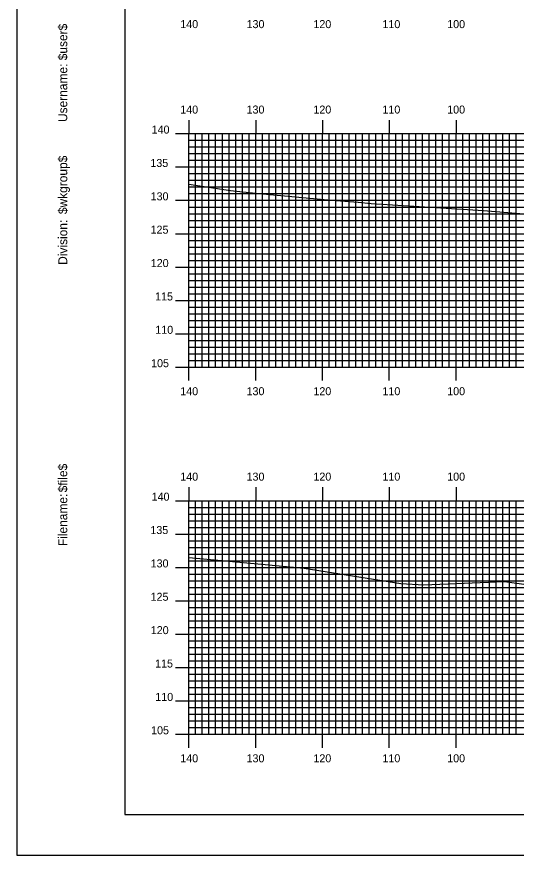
# Model space of a CAD drawing. Extents: x 1767300 to 1767643, y 442591 to 442811.
# Drawn here: x 1767300.1 to 1767375, y 442590.5 to 442716.2 of the extents above; entities that cross this region are included whole.
import ezdxf

# ---------------------------------------------------------------- set-up
doc = ezdxf.new("R2010")
doc.units = 0
for name, color, linetype in [('BORDER', 7, 'Continuous'), ('H_V ANNOTATION', 7, 'Continuous'), ('MAJOR', 7, 'Continuous'), ('MINOR', 7, 'Continuous'), ('PLOT BOUNDARY', 7, 'Continuous'), ('S_Roadway_Centerline', 7, 'Continuous')]:
    doc.layers.add(name, color=color, linetype=linetype)

msp = doc.modelspace()

# ---------------------------------------------------------------- linework, layer by layer
at = {"layer": 'BORDER'}
msp.add_lwpolyline([(1767316.34, 442596.67), (1767636.34, 442596.67), (1767636.34, 442806.67), (1767316.34, 442806.67)], close=True, dxfattribs=at)
at = {"layer": 'MAJOR'}
for p, q in [((1767325.94, 442700.67), (1767325.94, 442698.67)), ((1767335.94, 442700.67), (1767335.94, 442698.67)), ((1767345.94, 442700.67), (1767345.94, 442698.67)), ((1767355.94, 442700.67), (1767355.94, 442698.67)), ((1767365.94, 442700.67), (1767365.94, 442698.67)), ((1767323.93, 442698.67), (1767325.94, 442698.67)), ((1767325.94, 442698.67), (1767605.94, 442698.67)), ((1767325.94, 442663.67), (1767325.94, 442698.67)), ((1767325.94, 442663.67), (1767325.94, 442698.67)), ((1767325.94, 442698.67), (1767605.94, 442698.67)), ((1767335.94, 442663.67), (1767335.94, 442698.67)), ((1767345.94, 442663.67), (1767345.94, 442698.67)), ((1767355.94, 442663.67), (1767355.94, 442698.67)), ((1767365.94, 442663.67), (1767365.94, 442698.67)), ((1767323.93, 442693.67), (1767325.94, 442693.67)), ((1767325.94, 442693.67), (1767605.94, 442693.67)), ((1767323.93, 442688.67), (1767325.94, 442688.67)), ((1767325.94, 442688.67), (1767605.94, 442688.67)), ((1767323.93, 442683.67), (1767325.94, 442683.67)), ((1767325.94, 442683.67), (1767605.94, 442683.67)), ((1767323.93, 442678.67), (1767325.94, 442678.67)), ((1767325.94, 442678.67), (1767605.94, 442678.67)), ((1767323.93, 442673.67), (1767325.94, 442673.67)), ((1767325.94, 442673.67), (1767605.94, 442673.67)), ((1767323.93, 442668.67), (1767325.94, 442668.67)), ((1767325.94, 442668.67), (1767605.94, 442668.67)), ((1767323.93, 442663.67), (1767325.94, 442663.67)), ((1767325.94, 442663.67), (1767605.94, 442663.67)), ((1767325.94, 442663.67), (1767605.94, 442663.67)), ((1767325.94, 442661.66), (1767325.94, 442663.67)), ((1767335.94, 442661.66), (1767335.94, 442663.67)), ((1767345.94, 442661.66), (1767345.94, 442663.67)), ((1767355.94, 442661.66), (1767355.94, 442663.67)), ((1767365.94, 442661.66), (1767365.94, 442663.67)), ((1767325.94, 442645.67), (1767325.94, 442643.67)), ((1767335.94, 442645.67), (1767335.94, 442643.67)), ((1767345.94, 442645.67), (1767345.94, 442643.67)), ((1767355.94, 442645.67), (1767355.94, 442643.67)), ((1767365.94, 442645.67), (1767365.94, 442643.67)), ((1767323.93, 442643.67), (1767325.94, 442643.67)), ((1767325.94, 442643.67), (1767605.94, 442643.67)), ((1767325.94, 442608.67), (1767325.94, 442643.67)), ((1767325.94, 442608.67), (1767325.94, 442643.67)), ((1767325.94, 442643.67), (1767605.94, 442643.67)), ((1767335.94, 442608.67), (1767335.94, 442643.67)), ((1767345.94, 442608.67), (1767345.94, 442643.67)), ((1767355.94, 442608.67), (1767355.94, 442643.67)), ((1767365.94, 442608.67), (1767365.94, 442643.67)), ((1767323.93, 442638.67), (1767325.94, 442638.67)), ((1767325.94, 442638.67), (1767605.94, 442638.67)), ((1767323.93, 442633.67), (1767325.94, 442633.67)), ((1767325.94, 442633.67), (1767605.94, 442633.67)), ((1767323.93, 442628.67), (1767325.94, 442628.67)), ((1767325.94, 442628.67), (1767605.94, 442628.67)), ((1767323.93, 442623.67), (1767325.94, 442623.67)), ((1767325.94, 442623.67), (1767605.94, 442623.67)), ((1767323.93, 442618.67), (1767325.94, 442618.67)), ((1767325.94, 442618.67), (1767605.94, 442618.67)), ((1767323.93, 442613.67), (1767325.94, 442613.67)), ((1767325.94, 442613.67), (1767605.94, 442613.67)), ((1767323.93, 442608.67), (1767325.94, 442608.67)), ((1767325.94, 442608.67), (1767605.94, 442608.67)), ((1767325.94, 442608.67), (1767605.94, 442608.67)), ((1767325.94, 442606.66), (1767325.94, 442608.67)), ((1767335.94, 442606.66), (1767335.94, 442608.67)), ((1767345.94, 442606.66), (1767345.94, 442608.67)), ((1767355.94, 442606.66), (1767355.94, 442608.67)), ((1767365.94, 442606.66), (1767365.94, 442608.67))]:
    msp.add_line(p, q, dxfattribs=at)
at = {"layer": 'MINOR'}
for p, q in [((1767326.94, 442663.67), (1767326.94, 442698.67)), ((1767327.94, 442663.67), (1767327.94, 442698.67)), ((1767328.94, 442663.67), (1767328.94, 442698.67)), ((1767329.94, 442663.67), (1767329.94, 442698.67)), ((1767330.94, 442663.67), (1767330.94, 442698.67)), ((1767331.94, 442663.67), (1767331.94, 442698.67)), ((1767332.94, 442663.67), (1767332.94, 442698.67)), ((1767333.94, 442663.67), (1767333.94, 442698.67)), ((1767334.94, 442663.67), (1767334.94, 442698.67)), ((1767336.94, 442663.67), (1767336.94, 442698.67)), ((1767337.94, 442663.67), (1767337.94, 442698.67)), ((1767338.94, 442663.67), (1767338.94, 442698.67)), ((1767339.94, 442663.67), (1767339.94, 442698.67)), ((1767340.94, 442663.67), (1767340.94, 442698.67)), ((1767341.94, 442663.67), (1767341.94, 442698.67)), ((1767342.94, 442663.67), (1767342.94, 442698.67)), ((1767343.94, 442663.67), (1767343.94, 442698.67)), ((1767344.94, 442663.67), (1767344.94, 442698.67)), ((1767346.94, 442663.67), (1767346.94, 442698.67)), ((1767347.94, 442663.67), (1767347.94, 442698.67)), ((1767348.94, 442663.67), (1767348.94, 442698.67)), ((1767349.94, 442663.67), (1767349.94, 442698.67)), ((1767350.94, 442663.67), (1767350.94, 442698.67)), ((1767351.94, 442663.67), (1767351.94, 442698.67)), ((1767352.94, 442663.67), (1767352.94, 442698.67)), ((1767353.94, 442663.67), (1767353.94, 442698.67)), ((1767354.94, 442663.67), (1767354.94, 442698.67)), ((1767356.94, 442663.67), (1767356.94, 442698.67)), ((1767357.94, 442663.67), (1767357.94, 442698.67)), ((1767358.94, 442663.67), (1767358.94, 442698.67)), ((1767359.94, 442663.67), (1767359.94, 442698.67)), ((1767360.94, 442663.67), (1767360.94, 442698.67)), ((1767361.94, 442663.67), (1767361.94, 442698.67)), ((1767362.94, 442663.67), (1767362.94, 442698.67)), ((1767363.94, 442663.67), (1767363.94, 442698.67)), ((1767364.94, 442663.67), (1767364.94, 442698.67)), ((1767366.94, 442663.67), (1767366.94, 442698.67)), ((1767367.94, 442663.67), (1767367.94, 442698.67)), ((1767368.94, 442663.67), (1767368.94, 442698.67)), ((1767369.94, 442663.67), (1767369.94, 442698.67)), ((1767370.94, 442663.67), (1767370.94, 442698.67)), ((1767371.94, 442663.67), (1767371.94, 442698.67)), ((1767372.94, 442663.67), (1767372.94, 442698.67)), ((1767373.94, 442663.67), (1767373.94, 442698.67)), ((1767374.94, 442663.67), (1767374.94, 442698.67)), ((1767325.94, 442697.67), (1767605.94, 442697.67)), ((1767325.94, 442697.67), (1767327.94, 442697.67)), ((1767325.94, 442696.67), (1767605.94, 442696.67)), ((1767325.94, 442696.67), (1767327.94, 442696.67)), ((1767325.94, 442695.67), (1767605.94, 442695.67)), ((1767325.94, 442695.67), (1767327.94, 442695.67)), ((1767325.94, 442694.67), (1767605.94, 442694.67)), ((1767325.94, 442694.67), (1767327.94, 442694.67)), ((1767325.94, 442692.67), (1767605.94, 442692.67)), ((1767325.94, 442692.67), (1767327.94, 442692.67)), ((1767325.94, 442691.67), (1767605.94, 442691.67)), ((1767325.94, 442691.67), (1767327.94, 442691.67)), ((1767325.94, 442690.67), (1767605.94, 442690.67)), ((1767325.94, 442690.67), (1767327.94, 442690.67)), ((1767325.94, 442689.67), (1767605.94, 442689.67)), ((1767325.94, 442689.67), (1767327.94, 442689.67)), ((1767325.94, 442687.67), (1767605.94, 442687.67)), ((1767325.94, 442687.67), (1767327.94, 442687.67)), ((1767325.94, 442686.67), (1767605.94, 442686.67)), ((1767325.94, 442686.67), (1767327.94, 442686.67)), ((1767325.94, 442685.67), (1767605.94, 442685.67)), ((1767325.94, 442685.67), (1767327.94, 442685.67)), ((1767325.94, 442684.67), (1767605.94, 442684.67)), ((1767325.94, 442684.67), (1767327.94, 442684.67)), ((1767325.94, 442682.67), (1767605.94, 442682.67)), ((1767325.94, 442682.67), (1767327.94, 442682.67)), ((1767325.94, 442681.67), (1767605.94, 442681.67)), ((1767325.94, 442681.67), (1767327.94, 442681.67)), ((1767325.94, 442680.67), (1767605.94, 442680.67)), ((1767325.94, 442680.67), (1767327.94, 442680.67)), ((1767325.94, 442679.67), (1767605.94, 442679.67)), ((1767325.94, 442679.67), (1767327.94, 442679.67)), ((1767325.94, 442677.67), (1767605.94, 442677.67)), ((1767325.94, 442677.67), (1767327.94, 442677.67)), ((1767325.94, 442676.67), (1767605.94, 442676.67)), ((1767325.94, 442676.67), (1767327.94, 442676.67)), ((1767325.94, 442675.67), (1767605.94, 442675.67)), ((1767325.94, 442675.67), (1767327.94, 442675.67)), ((1767325.94, 442674.67), (1767605.94, 442674.67)), ((1767325.94, 442674.67), (1767327.94, 442674.67)), ((1767325.94, 442672.67), (1767605.94, 442672.67)), ((1767325.94, 442672.67), (1767327.94, 442672.67)), ((1767325.94, 442671.67), (1767605.94, 442671.67)), ((1767325.94, 442671.67), (1767327.94, 442671.67)), ((1767325.94, 442670.67), (1767605.94, 442670.67)), ((1767325.94, 442670.67), (1767327.94, 442670.67)), ((1767325.94, 442669.67), (1767605.94, 442669.67)), ((1767325.94, 442669.67), (1767327.94, 442669.67)), ((1767325.94, 442667.67), (1767605.94, 442667.67)), ((1767325.94, 442667.67), (1767327.94, 442667.67)), ((1767325.94, 442666.67), (1767605.94, 442666.67)), ((1767325.94, 442666.67), (1767327.94, 442666.67)), ((1767325.94, 442665.67), (1767605.94, 442665.67)), ((1767325.94, 442665.67), (1767327.94, 442665.67)), ((1767325.94, 442664.67), (1767605.94, 442664.67)), ((1767325.94, 442664.67), (1767327.94, 442664.67)), ((1767326.94, 442608.67), (1767326.94, 442643.67)), ((1767327.94, 442608.67), (1767327.94, 442643.67)), ((1767328.94, 442608.67), (1767328.94, 442643.67)), ((1767329.94, 442608.67), (1767329.94, 442643.67)), ((1767330.94, 442608.67), (1767330.94, 442643.67)), ((1767331.94, 442608.67), (1767331.94, 442643.67)), ((1767332.94, 442608.67), (1767332.94, 442643.67)), ((1767333.94, 442608.67), (1767333.94, 442643.67)), ((1767334.94, 442608.67), (1767334.94, 442643.67)), ((1767336.94, 442608.67), (1767336.94, 442643.67)), ((1767337.94, 442608.67), (1767337.94, 442643.67)), ((1767338.94, 442608.67), (1767338.94, 442643.67)), ((1767339.94, 442608.67), (1767339.94, 442643.67)), ((1767340.94, 442608.67), (1767340.94, 442643.67)), ((1767341.94, 442608.67), (1767341.94, 442643.67)), ((1767342.94, 442608.67), (1767342.94, 442643.67)), ((1767343.94, 442608.67), (1767343.94, 442643.67)), ((1767344.94, 442608.67), (1767344.94, 442643.67)), ((1767346.94, 442608.67), (1767346.94, 442643.67)), ((1767347.94, 442608.67), (1767347.94, 442643.67)), ((1767348.94, 442608.67), (1767348.94, 442643.67)), ((1767349.94, 442608.67), (1767349.94, 442643.67)), ((1767350.94, 442608.67), (1767350.94, 442643.67)), ((1767351.94, 442608.67), (1767351.94, 442643.67)), ((1767352.94, 442608.67), (1767352.94, 442643.67)), ((1767353.94, 442608.67), (1767353.94, 442643.67)), ((1767354.94, 442608.67), (1767354.94, 442643.67)), ((1767356.94, 442608.67), (1767356.94, 442643.67)), ((1767357.94, 442608.67), (1767357.94, 442643.67)), ((1767358.94, 442608.67), (1767358.94, 442643.67)), ((1767359.94, 442608.67), (1767359.94, 442643.67)), ((1767360.94, 442608.67), (1767360.94, 442643.67)), ((1767361.94, 442608.67), (1767361.94, 442643.67)), ((1767362.94, 442608.67), (1767362.94, 442643.67)), ((1767363.94, 442608.67), (1767363.94, 442643.67)), ((1767364.94, 442608.67), (1767364.94, 442643.67)), ((1767366.94, 442608.67), (1767366.94, 442643.67)), ((1767367.94, 442608.67), (1767367.94, 442643.67)), ((1767368.94, 442608.67), (1767368.94, 442643.67)), ((1767369.94, 442608.67), (1767369.94, 442643.67)), ((1767370.94, 442608.67), (1767370.94, 442643.67)), ((1767371.94, 442608.67), (1767371.94, 442643.67)), ((1767372.94, 442608.67), (1767372.94, 442643.67)), ((1767373.94, 442608.67), (1767373.94, 442643.67)), ((1767374.94, 442608.67), (1767374.94, 442643.67)), ((1767325.94, 442642.67), (1767605.94, 442642.67)), ((1767325.94, 442642.67), (1767327.94, 442642.67)), ((1767325.94, 442641.67), (1767605.94, 442641.67)), ((1767325.94, 442641.67), (1767327.94, 442641.67)), ((1767325.94, 442640.67), (1767605.94, 442640.67)), ((1767325.94, 442640.67), (1767327.94, 442640.67)), ((1767325.94, 442639.67), (1767605.94, 442639.67)), ((1767325.94, 442639.67), (1767327.94, 442639.67)), ((1767325.94, 442637.67), (1767605.94, 442637.67)), ((1767325.94, 442637.67), (1767327.94, 442637.67)), ((1767325.94, 442636.67), (1767605.94, 442636.67)), ((1767325.94, 442636.67), (1767327.94, 442636.67)), ((1767325.94, 442635.67), (1767605.94, 442635.67)), ((1767325.94, 442635.67), (1767327.94, 442635.67)), ((1767325.94, 442634.67), (1767605.94, 442634.67)), ((1767325.94, 442634.67), (1767327.94, 442634.67)), ((1767325.94, 442632.67), (1767605.94, 442632.67)), ((1767325.94, 442632.67), (1767327.94, 442632.67)), ((1767325.94, 442631.67), (1767605.94, 442631.67)), ((1767325.94, 442631.67), (1767327.94, 442631.67)), ((1767325.94, 442630.67), (1767605.94, 442630.67)), ((1767325.94, 442630.67), (1767327.94, 442630.67)), ((1767325.94, 442629.67), (1767605.94, 442629.67)), ((1767325.94, 442629.67), (1767327.94, 442629.67)), ((1767325.94, 442627.67), (1767605.94, 442627.67)), ((1767325.94, 442627.67), (1767327.94, 442627.67)), ((1767325.94, 442626.67), (1767605.94, 442626.67)), ((1767325.94, 442626.67), (1767327.94, 442626.67)), ((1767325.94, 442625.67), (1767605.94, 442625.67)), ((1767325.94, 442625.67), (1767327.94, 442625.67)), ((1767325.94, 442624.67), (1767605.94, 442624.67)), ((1767325.94, 442624.67), (1767327.94, 442624.67)), ((1767325.94, 442622.67), (1767605.94, 442622.67)), ((1767325.94, 442622.67), (1767327.94, 442622.67)), ((1767325.94, 442621.67), (1767605.94, 442621.67)), ((1767325.94, 442621.67), (1767327.94, 442621.67)), ((1767325.94, 442620.67), (1767605.94, 442620.67)), ((1767325.94, 442620.67), (1767327.94, 442620.67)), ((1767325.94, 442619.67), (1767605.94, 442619.67)), ((1767325.94, 442619.67), (1767327.94, 442619.67)), ((1767325.94, 442617.67), (1767605.94, 442617.67)), ((1767325.94, 442617.67), (1767327.94, 442617.67)), ((1767325.94, 442616.67), (1767605.94, 442616.67)), ((1767325.94, 442616.67), (1767327.94, 442616.67)), ((1767325.94, 442615.67), (1767605.94, 442615.67)), ((1767325.94, 442615.67), (1767327.94, 442615.67)), ((1767325.94, 442614.67), (1767605.94, 442614.67)), ((1767325.94, 442614.67), (1767327.94, 442614.67)), ((1767325.94, 442612.67), (1767605.94, 442612.67)), ((1767325.94, 442612.67), (1767327.94, 442612.67)), ((1767325.94, 442611.67), (1767605.94, 442611.67)), ((1767325.94, 442611.67), (1767327.94, 442611.67)), ((1767325.94, 442610.67), (1767605.94, 442610.67)), ((1767325.94, 442610.67), (1767327.94, 442610.67)), ((1767325.94, 442609.67), (1767605.94, 442609.67)), ((1767325.94, 442609.67), (1767327.94, 442609.67))]:
    msp.add_line(p, q, dxfattribs=at)
at = {"layer": 'PLOT BOUNDARY'}
msp.add_lwpolyline([(1767300.15, 442590.55), (1767640.15, 442590.55), (1767640.15, 442810.55), (1767300.15, 442810.55)], close=True, dxfattribs=at)
at = {"layer": 'S_Roadway_Centerline'}
for points in [[(1767325.94, 442691.07), (1767332.17, 442690.16), (1767335.91, 442689.72), (1767347.28, 442688.68), (1767351.27, 442688.39), (1767353.21, 442688.2), (1767370.06, 442687.16), (1767379.16, 442686.41)], [(1767325.94, 442635.18), (1767336.82, 442634.14), (1767343.21, 442633.55), (1767357.68, 442631.28), (1767361.13, 442631.07), (1767373.18, 442631.54), (1767381.58, 442630.39)]]:
    msp.add_lwpolyline(points, dxfattribs=at)

# ---------------------------------------------------------------- texts
at = {"layer": 'BORDER'}
for s, p in [('$user$', (1767307.71, 442709.65)), ('Username:', (1767307.71, 442700.4)), ('$wkgroup$', (1767307.71, 442686.6)), ('Division:', (1767307.71, 442679)), ('$file$', (1767307.71, 442644.92)), ('Filename:', (1767307.71, 442636.86))]:
    msp.add_text(s, height=1.339, rotation=90, dxfattribs=at).set_placement(p)
at = {"layer": 'H_V ANNOTATION'}
for s, p in [('140', (1767324.64, 442714.47)), ('130', (1767334.57, 442714.47)), ('120', (1767344.58, 442714.47)), ('110', (1767354.92, 442714.47)), ('100', (1767364.62, 442714.47)), ('140', (1767324.64, 442701.67)), ('130', (1767334.57, 442701.67)), ('120', (1767344.58, 442701.67)), ('110', (1767354.92, 442701.67)), ('100', (1767364.62, 442701.67)), ('140', (1767320.35, 442698.67)), ('135', (1767320.16, 442693.67)), ('130', (1767320.2, 442688.67)), ('125', (1767320.19, 442683.67)), ('120', (1767320.22, 442678.67)), ('115', (1767320.87, 442673.67)), ('110', (1767320.9, 442668.67)), ('105', (1767320.27, 442663.67)), ('140', (1767324.64, 442659.47)), ('130', (1767334.57, 442659.47)), ('120', (1767344.58, 442659.47)), ('110', (1767354.92, 442659.47)), ('100', (1767364.62, 442659.47)), ('140', (1767324.64, 442646.67)), ('130', (1767334.57, 442646.67)), ('120', (1767344.58, 442646.67)), ('110', (1767354.92, 442646.67)), ('100', (1767364.62, 442646.67)), ('140', (1767320.35, 442643.67)), ('135', (1767320.16, 442638.67)), ('130', (1767320.2, 442633.67)), ('125', (1767320.19, 442628.67)), ('120', (1767320.22, 442623.67)), ('115', (1767320.87, 442618.67)), ('110', (1767320.9, 442613.67)), ('105', (1767320.27, 442608.67)), ('140', (1767324.64, 442604.47)), ('130', (1767334.57, 442604.47)), ('120', (1767344.58, 442604.47)), ('110', (1767354.92, 442604.47)), ('100', (1767364.62, 442604.47))]:
    msp.add_text(s, height=1.2, dxfattribs=at).set_placement(p)
at = {"layer": 'MAJOR'}
for p in [(1767325.93, 442663.67), (1767325.93, 442608.67)]:
    msp.add_text('-', height=0.012, dxfattribs=at).set_placement(p)

doc.saveas('drawing.dxf')
